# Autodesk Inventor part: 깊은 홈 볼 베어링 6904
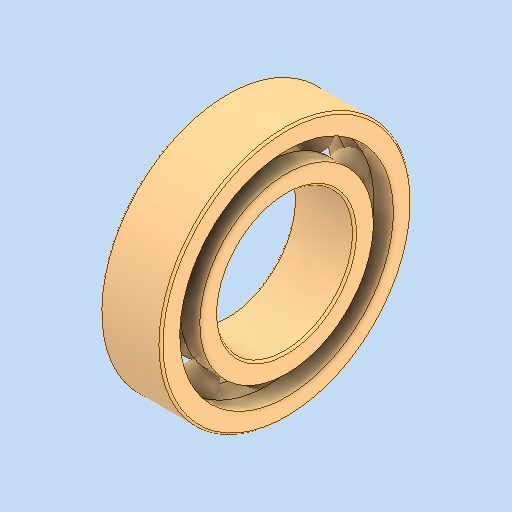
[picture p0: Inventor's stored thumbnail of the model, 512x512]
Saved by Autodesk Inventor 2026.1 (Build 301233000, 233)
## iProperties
Created: 2025-09
Part Number: 깊은 홈 볼 베어링 6904
Material: 강철, 연강
Description: 깊은 그루브 볼 베어링
Document SubType Name: Modeling
Designer: PC-30
Density: 7.85 g/cm^3
Appearance: 기본값
Author: jhkim
Sending System: Autodesk Inventor 2026
Preprocessor: ST-DEVELOPER v20.1
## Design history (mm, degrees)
feature "Solid1"
feature "Solid1:1"
feature "Solid1:2"
feature "Solid1:3"
feature "Solid1:4"
feature "Solid1:5"
feature "Solid1:6"
feature "Solid1:7"
feature "Solid1:8"
feature "Solid1:9"
feature "Solid1:10"
feature "Solid1:11"
node "솔리드1"
node "솔리드2"
node "솔리드3"
node "솔리드4"
node "솔리드5"
node "솔리드6"
node "솔리드7"
node "솔리드8"
node "솔리드9"
node "솔리드10"
node "솔리드11"
node "솔리드12"
